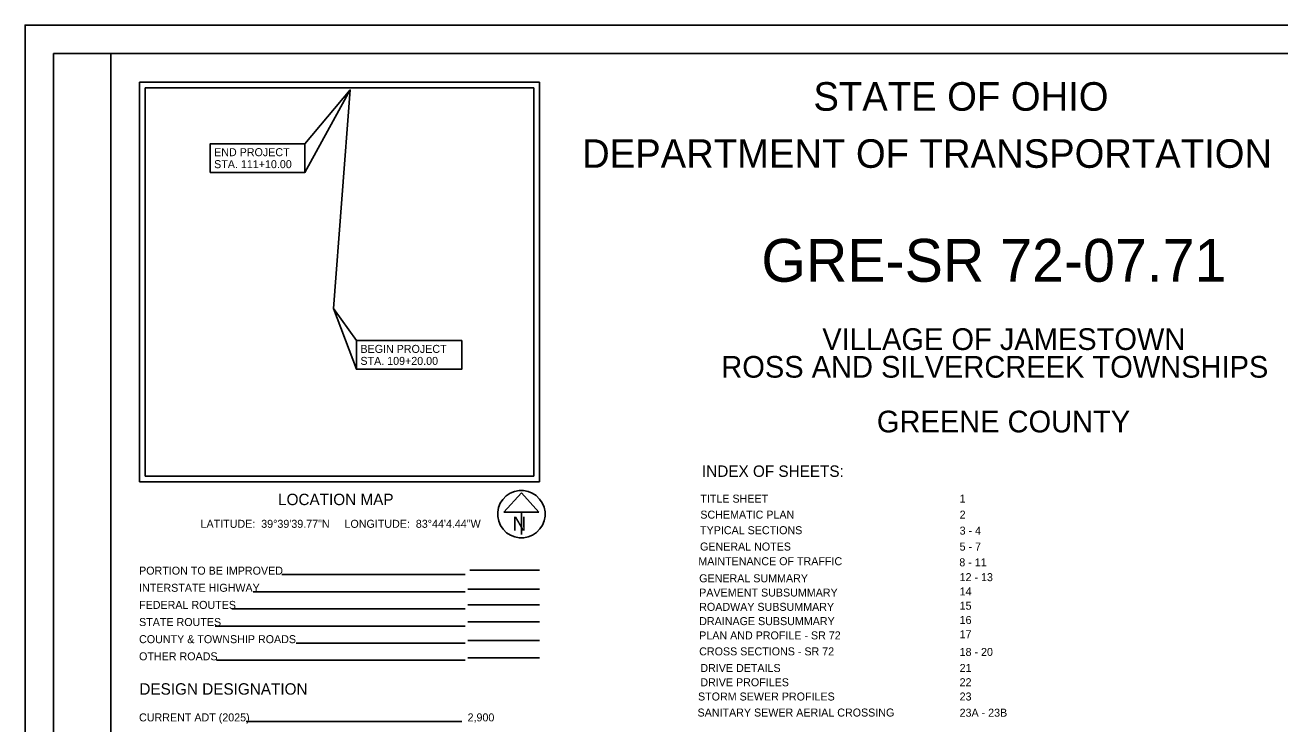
# Model space of a CAD drawing. Extents: x -4 to 116, y -17 to 29.
# Drawn here: x 48.48 to 70.44, y -4.84 to 7.39 of the extents above; entities that cross this region are included whole.
import ezdxf

# ---------------------------------------------------------------- set-up
doc = ezdxf.new("R2010")
doc.units = 0
for name, color, linetype in [('Default', 7, 'Continuous'), ('SH_Border', 7, 'Continuous'), ('SH_Cut_Line', 7, 'Continuous'), ('SH_Data', 7, 'Continuous'), ('SH_Text', 7, 'Continuous')]:
    doc.layers.add(name, color=color, linetype=linetype)

msp = doc.modelspace()

# ---------------------------------------------------------------- linework, layer by layer
at = {"layer": 'Default'}
for points in [[(53.379, 5.314), (54.173, 6.26), (53.379, 4.814)], [(51.721, 4.814), (53.379, 4.814), (53.379, 5.314), (51.721, 5.314)], [(54.281, 1.869), (53.879, 2.429), (54.281, 1.369)], [(54.281, 1.369), (56.125, 1.369), (56.125, 1.869), (54.281, 1.869)]]:
    msp.add_lwpolyline(points, close=True, dxfattribs=at)
at = {"layer": 'SH_Border'}
for points in [[(48.983, 6.895), (49.983, 6.895), (49.983, -14.105), (48.983, -14.105)], [(49.983, 6.895), (81.983, 6.895), (81.983, -14.105), (49.983, -14.105)]]:
    msp.add_lwpolyline(points, close=True, dxfattribs=at)
at = {"layer": 'SH_Cut_Line'}
msp.add_lwpolyline([(48.483, -14.605), (82.483, -14.605), (82.483, 7.395), (48.483, 7.395)], close=True, dxfattribs=at)
at = {"layer": 'SH_Data'}
for p, q in [((50.483, 6.395), (57.483, 6.395)), ((50.483, 6.395), (50.483, -0.605)), ((57.483, 6.395), (57.483, -0.605)), ((50.583, 6.295), (50.583, -0.505)), ((50.583, 6.295), (57.383, 6.295)), ((57.383, 6.295), (57.383, -0.505)), ((50.483, -0.605), (57.483, -0.605)), ((50.583, -0.505), (57.383, -0.505)), ((50.583, -0.505), (50.583, -0.505)), ((57.168, -0.796), (56.86, -1.137)), ((57.475, -1.137), (57.168, -0.796)), ((56.86, -1.137), (57.475, -1.137)), ((57.168, -1.137), (57.168, -1.524)), ((57.168, -1.17), (57.168, -1.17)), ((57.168, -1.17), (57.168, -1.17)), ((56.266, -2.15), (57.483, -2.15)), ((56.183, -2.229), (52.977, -2.229)), ((56.183, -2.529), (52.473, -2.529)), ((57.483, -2.485), (56.233, -2.485)), ((56.183, -2.829), (52.103, -2.829)), ((57.483, -2.756), (56.233, -2.756)), ((57.483, -3.056), (56.233, -3.056)), ((56.183, -3.129), (51.812, -3.129)), ((56.183, -3.429), (53.229, -3.429)), ((57.483, -3.383), (56.233, -3.383)), ((56.183, -3.729), (51.83, -3.729)), ((57.483, -3.683), (56.233, -3.683)), ((56.126, -4.799), (52.354, -4.799))]:
    msp.add_line(p, q, dxfattribs=at)
msp.add_arc((57.168, -1.17), 0.415, 129.7798, 129.7633, dxfattribs=at)
at = {"layer": 'SH_Text'}
msp.add_line((54.173, 6.26), (53.879, 2.429), dxfattribs=at)

# ---------------------------------------------------------------- texts
at = {"layer": 'Default'}
for s, p in [('END PROJECT', (51.791, 5.099)), ('STA. 111+10.00', (51.791, 4.889)), ('BEGIN PROJECT', (54.351, 1.654)), ('STA. 109+20.00', (54.351, 1.444))]:
    msp.add_text(s, height=0.14, dxfattribs=at).set_placement(p)
at = {"layer": 'SH_Data'}
for s, height, p in [('N', 0.25, (57.012, -1.461)), ('DESIGN DESIGNATION', 0.2, (50.483, -4.331))]:
    msp.add_text(s, height=height, dxfattribs=at).set_placement(p)
at = {"layer": 'SH_Text'}
for s, height, p in [('STATE OF OHIO', 0.5, (62.278, 5.895)), ('DEPARTMENT OF TRANSPORTATION', 0.5, (58.23, 4.895)), ('GRE-SR 72-07.71', 0.75, (61.367, 2.9)), ('VILLAGE OF JAMESTOWN', 0.38, (62.433, 1.705)), ('ROSS AND SILVERCREEK TOWNSHIPS', 0.38, (60.666, 1.22)), ('GREENE COUNTY', 0.38, (63.388, 0.262)), ('INDEX OF SHEETS:', 0.2, (60.328, -0.517)), ('LOCATION MAP', 0.2, (52.91, -1.012)), ('TITLE SHEET ', 0.14, (60.299, -0.968)), ('1', 0.14, (64.836, -0.968)), ('LATITUDE:  39°39\'39.77"N     LONGITUDE:  83°44\'4.44"W', 0.14, (51.554, -1.409)), ('SCHEMATIC PLAN ', 0.14, (60.299, -1.248)), ('2', 0.14, (64.836, -1.248)), ('TYPICAL SECTIONS ', 0.14, (60.294, -1.521)), ('3 - 4', 0.14, (64.836, -1.528)), ('GENERAL NOTES ', 0.14, (60.293, -1.807)), ('5 - 7', 0.14, (64.836, -1.808)), ('MAINTENANCE OF TRAFFIC', 0.14, (60.264, -2.064)), ('8 - 11', 0.14, (64.831, -2.083)), ('PORTION TO BE IMPROVED', 0.14, (50.478, -2.229)), ('INTERSTATE HIGHWAY', 0.14, (50.478, -2.529)), ('GENERAL SUMMARY', 0.14, (60.279, -2.363)), ('12 - 13', 0.14, (64.836, -2.343)), ('PAVEMENT SUBSUMMARY', 0.14, (60.279, -2.613)), ('14', 0.14, (64.836, -2.593)), ('FEDERAL ROUTES', 0.14, (50.478, -2.829)), ('ROADWAY SUBSUMMARY', 0.14, (60.279, -2.863)), ('15', 0.14, (64.836, -2.843)), ('STATE ROUTES', 0.14, (50.478, -3.129)), ('DRAINAGE SUBSUMMARY', 0.14, (60.279, -3.113)), ('16', 0.14, (64.836, -3.093)), ('COUNTY & TOWNSHIP ROADS', 0.14, (50.478, -3.429)), ('PLAN AND PROFILE - SR 72', 0.14, (60.279, -3.363)), ('17', 0.14, (64.836, -3.343)), ('CROSS SECTIONS - SR 72', 0.14, (60.279, -3.643)), ('18 - 20', 0.14, (64.836, -3.653)), ('OTHER ROADS', 0.14, (50.478, -3.729)), ('DRIVE DETAILS', 0.14, (60.299, -3.934)), ('21', 0.14, (64.836, -3.933)), ('DRIVE PROFILES', 0.14, (60.299, -4.184)), ('22', 0.14, (64.836, -4.183)), ('STORM SEWER PROFILES', 0.14, (60.258, -4.433)), ('23', 0.14, (64.836, -4.433)), ('SANITARY SEWER AERIAL CROSSING', 0.14, (60.25, -4.714)), ('23A - 23B', 0.14, (64.836, -4.717)), ('CURRENT ADT (2025)', 0.14, (50.478, -4.799)), ('2,900', 0.14, (56.226, -4.799))]:
    msp.add_text(s, height=height, dxfattribs=at).set_placement(p)

doc.saveas('drawing.dxf')
